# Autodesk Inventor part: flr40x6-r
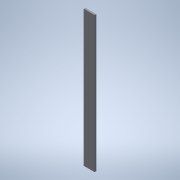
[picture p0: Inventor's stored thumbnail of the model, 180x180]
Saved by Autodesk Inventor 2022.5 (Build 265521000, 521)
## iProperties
Created: 2016-12
Part Number: flr40x6-r
Material: 一般
Document SubType Name: Modeling
Designer: imaocorp
Density: 1 g/cm^3
Appearance: 既定
Author: imaocorp
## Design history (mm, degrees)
node "flr40x6-r.x_t1"
node "flr40x6-r"
node "Base1"
